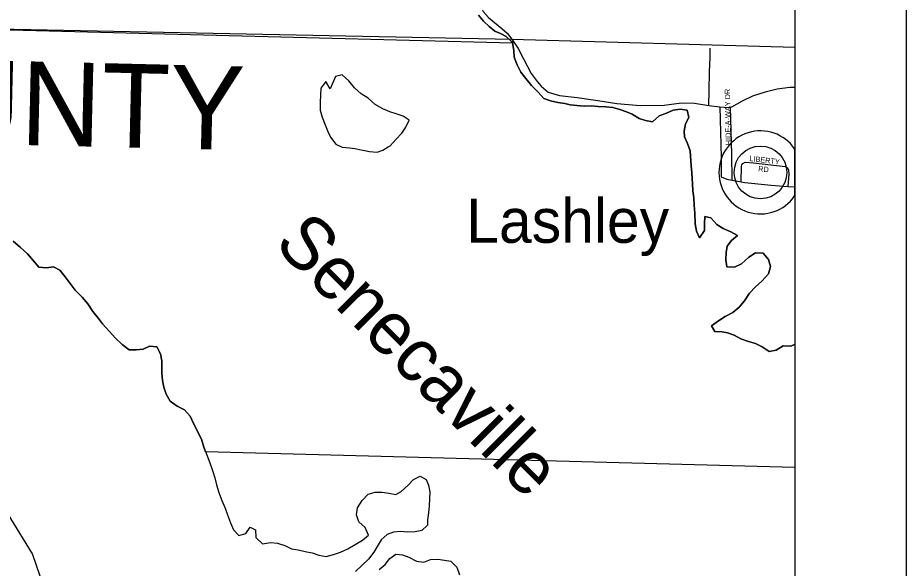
# Model space of a CAD drawing. Extents: x -22 to 431, y -18 to 160.
# Drawn here: x 330.402 to 331.995, y 157.754 to 158.739 of the extents above; entities that cross this region are included whole.
import ezdxf

# ---------------------------------------------------------------- set-up
doc = ezdxf.new("R2010")
doc.units = 0
for name, color, linetype in [('GM_X_Adjacent_County', 7, 'Continuous'), ('GM_X_Airport_Text_Class_2', 7, 'Continuous'), ('GM_X_County_ROW', 7, 'Continuous'), ('GM_X_County_Subdivision', 7, 'Continuous'), ('GM_X_Major_River_Text', 7, 'Continuous'), ('GM_X_Minor_River_Text', 7, 'Continuous'), ('GM_X_Section', 7, 'Continuous'), ('GM_X_Township_Road', 7, 'Continuous'), ('GM_X_Township_ROW', 7, 'Continuous'), ('GM_X_Township_Subdivision', 7, 'Continuous'), ('GM_X_Unincorporated_Text', 7, 'Continuous')]:
    doc.layers.add(name, color=color, linetype=linetype)

msp = doc.modelspace()

# ---------------------------------------------------------------- linework, layer by layer
at = {"layer": 'GM_X_County_ROW'}
for points in [[(331.1984, 158.868), (331.1996, 158.8569), (331.1999, 158.855), (331.2046, 158.8285), (331.2131, 158.8009), (331.2206, 158.7821), (331.2296, 158.7651), (331.2363, 158.7508), (331.246, 158.74), (331.2571, 158.731), (331.2698, 158.72), (331.2794, 158.7119), (331.2882, 158.7011)], [(331.2882, 158.7011), (331.299, 158.6846), (331.3091, 158.6657), (331.3227, 158.6394), (331.3334, 158.6256), (331.3405, 158.6168), (331.3529, 158.6064), (331.3733, 158.6004), (331.4051, 158.5969), (331.4422, 158.5915), (331.4763, 158.5862), (331.5179, 158.5822), (331.5612, 158.5828), (331.5923, 158.5869), (331.6156, 158.5868), (331.6409, 158.5825), (331.6605, 158.58), (331.6688, 158.5791), (331.6756, 158.5787), (331.6798, 158.5793), (331.6821, 158.5797), (331.7016, 158.5905), (331.7199, 158.5997), (331.7442, 158.6074), (331.7636, 158.6121), (331.786, 158.6152), (331.7949, 158.6152)], [(330.3922, 155.9159), (330.4518, 156.0381), (330.5552, 156.1431), (330.5592, 156.1465), (330.7531, 156.2605), (330.8962, 156.3618), (330.9146, 156.3744), (330.9622, 156.4236), (330.9704, 156.6616), (330.9659, 156.6885), (330.9511, 156.723), (330.9429, 156.7783), (330.9425, 156.8344), (330.9683, 156.9486), (330.9647, 156.9722), (330.9594, 156.9861), (330.9462, 156.9983), (330.4458, 157.5656), (330.4767, 157.6399), (330.4285, 157.7791), (330.323, 157.9508)]]:
    msp.add_lwpolyline(points, dxfattribs=at)
at = {"layer": 'GM_X_Major_River_Text'}
for p, q in [((330.1206, 158.7248), (331.2882, 158.7011)), ((331.2882, 158.7011), (331.7949, 158.6867))]:
    msp.add_line(p, q, dxfattribs=at)
at = {"layer": 'GM_X_Minor_River_Text'}
msp.add_lwpolyline([(331.6409, 158.5825), (331.6418, 158.6093), (331.6424, 158.6429), (331.6433, 158.6683), (331.6435, 158.6852)], dxfattribs=at)
at = {"layer": 'GM_X_Section'}
msp.add_line((331.7949, 159.9199), (331.7949, 147.6799), dxfattribs=at)
msp.add_lwpolyline([(319.3549, 160.1199), (331.9949, 160.1199), (331.9949, 147.4799), (319.3549, 147.4799)], close=True, dxfattribs=at)
at = {"layer": 'GM_X_Township_Road'}
msp.add_line((331.7949, 158.4203), (331.7949, 158.5048), dxfattribs=at)
msp.add_circle((331.7336, 158.4625), 0.0472, dxfattribs=at)
msp.add_arc((331.7336, 158.4625), 0.0744, 34.6154, 325.3846, dxfattribs=at)
at = {"layer": 'GM_X_Township_ROW'}
for points in [[(331.6605, 158.58), (331.663, 158.4894), (331.6629, 158.4548), (331.6731, 158.4503), (331.6829, 158.4485), (331.6987, 158.4457), (331.7057, 158.4445), (331.7526, 158.4395), (331.7825, 158.4373), (331.7949, 158.4364)], [(331.6829, 158.4485), (331.6823, 158.4954), (331.6798, 158.5793)], [(331.6987, 158.4457), (331.6993, 158.4734), (331.7004, 158.476), (331.702, 158.4787), (331.7061, 158.4809), (331.7209, 158.4798), (331.7781, 158.4732), (331.7819, 158.4705), (331.7841, 158.4663), (331.7845, 158.4591), (331.7825, 158.4373)]]:
    msp.add_lwpolyline(points, dxfattribs=at)
at = {"layer": 'GM_X_Township_Subdivision'}
for p, q in [((329.9956, 158.7279), (331.2892, 158.6947)), ((331.7949, 157.9339), (330.7391, 157.962))]:
    msp.add_line(p, q, dxfattribs=at)
for points in [[(331.2892, 158.6947), (331.2874, 158.6969), (331.2775, 158.7062), (331.2679, 158.711), (331.2573, 158.7155), (331.2474, 158.7241), (331.2374, 158.7334), (331.2279, 158.7439)], [(331.2279, 158.7439), (331.2374, 158.7334), (331.2474, 158.7241), (331.2573, 158.7155), (331.2679, 158.711), (331.2775, 158.7062), (331.2874, 158.6969), (331.2892, 158.6947)], [(331.7949, 158.1544), (331.7876, 158.1513), (331.774, 158.152), (331.7619, 158.1439), (331.7491, 158.1419), (331.7369, 158.1498), (331.7244, 158.1558), (331.7119, 158.1595), (331.6986, 158.1644), (331.6864, 158.1708), (331.6743, 158.1752), (331.6648, 158.1771), (331.6516, 158.1777), (331.6458, 158.1879), (331.6583, 158.1964), (331.6704, 158.2044), (331.6839, 158.2113), (331.6956, 158.2213), (331.705, 158.2327), (331.714, 158.246), (331.7249, 158.2575), (331.7362, 158.2674), (331.7479, 158.2811), (331.7516, 158.2937), (331.7477, 158.3062), (331.7382, 158.3179), (331.7246, 158.3182), (331.7125, 158.3105), (331.6993, 158.2987), (331.6869, 158.2925), (331.6736, 158.2936), (331.6713, 158.3061), (331.6719, 158.319), (331.6738, 158.3304), (331.6817, 158.3407), (331.6926, 158.3495), (331.6804, 158.3558), (331.6668, 158.3618), (331.6554, 158.3689), (331.6447, 158.3814), (331.6337, 158.3836), (331.6334, 158.3703), (331.6335, 158.3582), (331.6241, 158.3452), (331.6187, 158.3573), (331.6168, 158.3706), (331.6159, 158.3896), (331.615, 158.4036), (331.6142, 158.4169), (331.6122, 158.4297), (331.6118, 158.4423), (331.6114, 158.4517), (331.6105, 158.462), (331.6093, 158.4745), (331.6077, 158.501), (331.603, 158.5143), (331.5977, 158.5264), (331.5968, 158.5363), (331.599, 158.5492), (331.6054, 158.561), (331.6023, 158.5742), (331.5894, 158.5757), (331.5773, 158.5741), (331.5649, 158.5687), (331.552, 158.564), (331.5403, 158.5533), (331.5278, 158.5555), (331.5161, 158.5593), (331.5035, 158.5668), (331.4937, 158.5709), (331.4815, 158.575), (331.4687, 158.5787), (331.4565, 158.5798), (331.4425, 158.5808), (331.43, 158.5815), (331.4175, 158.5814), (331.4047, 158.5821), (331.3925, 158.5835), (331.3827, 158.5857), (331.3702, 158.5875), (331.3573, 158.5905), (331.3455, 158.595), (331.3349, 158.6063), (331.3231, 158.618), (331.3132, 158.6304), (331.304, 158.6418), (331.2975, 158.655), (331.2924, 158.6687), (331.2913, 158.6806), (331.2892, 158.6947)], [(331.2892, 158.6947), (331.2913, 158.6806), (331.2924, 158.6687), (331.2975, 158.655), (331.304, 158.6418), (331.3132, 158.6304), (331.3231, 158.618), (331.3349, 158.6063), (331.3455, 158.595), (331.3573, 158.5905), (331.3702, 158.5875), (331.3827, 158.5857), (331.3925, 158.5835), (331.4047, 158.5821), (331.4175, 158.5814), (331.43, 158.5815), (331.4425, 158.5808), (331.4565, 158.5798), (331.4687, 158.5787), (331.4815, 158.575), (331.4937, 158.5709), (331.5035, 158.5668), (331.5161, 158.5593), (331.5278, 158.5555), (331.5403, 158.5533), (331.552, 158.564), (331.5649, 158.5687), (331.5773, 158.5741), (331.5894, 158.5757), (331.6023, 158.5742), (331.6054, 158.561), (331.599, 158.5492), (331.5968, 158.5363), (331.5977, 158.5264), (331.603, 158.5143), (331.6077, 158.501), (331.6093, 158.4745), (331.6105, 158.462), (331.6114, 158.4517), (331.6118, 158.4423), (331.6122, 158.4297), (331.6142, 158.4169), (331.615, 158.4036), (331.6159, 158.3896), (331.6168, 158.3706), (331.6187, 158.3573), (331.6241, 158.3452), (331.6335, 158.3582), (331.6334, 158.3703), (331.6337, 158.3836), (331.6447, 158.3814), (331.6554, 158.3689), (331.6668, 158.3618), (331.6804, 158.3558), (331.6926, 158.3495), (331.6817, 158.3407), (331.6738, 158.3304), (331.6719, 158.319), (331.6713, 158.3061), (331.6736, 158.2936), (331.6869, 158.2925), (331.6993, 158.2987), (331.7125, 158.3105), (331.7246, 158.3182), (331.7382, 158.3179), (331.7477, 158.3062), (331.7516, 158.2937), (331.7479, 158.2811), (331.7362, 158.2674), (331.7249, 158.2575), (331.714, 158.246), (331.705, 158.2327), (331.6956, 158.2213), (331.6839, 158.2113), (331.6704, 158.2044), (331.6583, 158.1964), (331.6458, 158.1879), (331.6516, 158.1777), (331.6648, 158.1771), (331.6743, 158.1752), (331.6864, 158.1708), (331.6986, 158.1644), (331.7119, 158.1595), (331.7244, 158.1558), (331.7369, 158.1498), (331.7491, 158.1419), (331.7619, 158.1439), (331.774, 158.152), (331.7876, 158.1513), (331.7949, 158.1544)], [(331.0661, 158.508), (331.0699, 158.5102), (331.0808, 158.522), (331.0906, 158.533), (331.0981, 158.5433), (331.1037, 158.5563), (331.093, 158.5634), (331.0805, 158.5671), (331.0695, 158.5712), (331.0566, 158.5765), (331.0429, 158.5844), (331.0304, 158.5953), (331.0178, 158.6032), (331.006, 158.6141), (330.9957, 158.6266), (330.9839, 158.6371), (330.9718, 158.634), (330.9621, 158.612)], [(330.9621, 158.612), (330.9548, 158.6256), (330.9454, 158.6134), (330.9448, 158.6009), (330.9441, 158.588), (330.9445, 158.5739), (330.948, 158.5614), (330.9534, 158.5478), (330.958, 158.5357), (330.9626, 158.5258), (330.9725, 158.513), (330.9839, 158.5078), (330.9972, 158.5067), (331.0066, 158.5056), (331.018, 158.503), (331.0328, 158.5001), (331.0468, 158.499), (331.0566, 158.5025), (331.0661, 158.508)], [(330.394, 158.3393), (330.4073, 158.328), (330.4198, 158.3167), (330.4305, 158.3042), (330.44, 158.2925), (330.4537, 158.2918), (330.4665, 158.2934), (330.4775, 158.2871), (330.4871, 158.2757), (330.5054, 158.2516), (330.5176, 158.2391), (330.5282, 158.2271), (330.537, 158.2131), (330.5469, 158.201), (330.5542, 158.1912), (330.5668, 158.1776), (330.5771, 158.1659), (330.5892, 158.1543), (330.6018, 158.1449), (330.6143, 158.1449), (330.6271, 158.1458), (330.6385, 158.1515), (330.6517, 158.1501), (330.6579, 158.1376), (330.6606, 158.1248), (330.6603, 158.1122), (330.6603, 158.1028), (330.6619, 158.0899), (330.6639, 158.0777), (330.6685, 158.0653), (330.6758, 158.0528), (330.6883, 158.0438), (330.7012, 158.0374), (330.7111, 158.0261), (330.718, 158.0117), (330.7318, 157.9845), (330.7361, 157.9705), (330.7418, 157.9546), (330.7464, 157.9425), (330.7514, 157.9288), (330.7557, 157.9152), (330.7588, 157.9031), (330.7627, 157.8891), (330.768, 157.8751), (330.7742, 157.8611), (330.7784, 157.8494), (330.7834, 157.835), (330.7888, 157.8221), (330.7987, 157.8123), (330.8112, 157.8158), (330.8187, 157.8272), (330.8282, 157.8224), (330.829, 157.8087), (330.8408, 157.7974)], [(330.7391, 157.962), (330.7361, 157.9705), (330.7318, 157.9845), (330.718, 158.0117), (330.7111, 158.0261), (330.7012, 158.0374), (330.6883, 158.0438), (330.6758, 158.0528), (330.6685, 158.0653), (330.6639, 158.0777), (330.6619, 158.0899), (330.6603, 158.1028), (330.6603, 158.1122), (330.6606, 158.1248), (330.6579, 158.1376), (330.6517, 158.1501), (330.6385, 158.1515), (330.6271, 158.1458), (330.6143, 158.1449), (330.6018, 158.1449), (330.5892, 158.1543), (330.5771, 158.1659), (330.5668, 158.1776), (330.5542, 158.1912), (330.5469, 158.201), (330.537, 158.2131), (330.5282, 158.2271), (330.5176, 158.2391), (330.5054, 158.2516), (330.4871, 158.2757), (330.4775, 158.2871), (330.4665, 158.2934), (330.4537, 158.2918), (330.44, 158.2925), (330.4305, 158.3042), (330.4198, 158.3167), (330.4073, 158.328), (330.394, 158.3393)], [(330.8408, 157.7974), (330.8552, 157.7994), (330.868, 157.7984), (330.8809, 157.7943), (330.8927, 157.7883), (330.9048, 157.7865), (330.9173, 157.7835), (330.9298, 157.7809), (330.942, 157.7772), (330.9552, 157.7746), (330.9685, 157.7781), (330.9806, 157.7824), (330.9938, 157.7885), (331.0074, 157.7958), (331.0202, 157.8039), (331.0311, 157.8127), (331.025, 157.8263), (331.0139, 157.8365), (331.0097, 157.8493), (331.0111, 157.8619), (331.0198, 157.8748), (331.0303, 157.8859), (331.0428, 157.8898), (331.0556, 157.8895), (331.0677, 157.888), (331.0799, 157.8858), (331.0897, 157.8912), (331.1021, 157.9023), (331.1115, 157.9122), (331.1236, 157.9187), (331.1346, 157.9127), (331.1388, 157.9025), (331.1408, 157.8904), (331.1405, 157.8779), (331.1398, 157.8653), (331.1387, 157.8528), (331.1369, 157.8403), (331.1366, 157.8308), (331.1264, 157.8209), (331.1147, 157.8189), (331.1015, 157.8181), (331.0886, 157.8195), (331.0761, 157.8183), (331.0644, 157.8137), (331.0535, 157.8045), (331.0467, 157.7927), (331.0404, 157.782), (331.031, 157.7698), (331.0193, 157.7587), (331.008, 157.7477)], [(331.0504, 157.751), (331.0606, 157.7605), (331.0692, 157.7708), (331.0798, 157.7785), (331.0922, 157.7774), (331.1036, 157.7733), (331.1169, 157.7662), (331.1302, 157.7644), (331.1419, 157.769), (331.1551, 157.7699), (331.1672, 157.768), (331.1786, 157.7662), (331.1893, 157.7557), (331.1939, 157.7417)]]:
    msp.add_lwpolyline(points, dxfattribs=at)

# ---------------------------------------------------------------- texts
at = {"layer": 'GM_X_Adjacent_County'}
msp.add_text('Lashley', height=0.07891, rotation=0, dxfattribs=at).set_placement((331.2062, 158.3364))
at = {"layer": 'GM_X_Airport_Text_Class_2'}
msp.add_text('Senecaville', height=0.094697, rotation=315.0021, dxfattribs=at).set_placement((330.8594, 158.3321))
at = {"layer": 'GM_X_County_Subdivision'}
for s, rotation, p in [('HIDE-A-WAY DR', 91.0603, (331.6808, 158.5113)), ('LIBERTY', 353.2341, (331.7134, 158.483)), ('RD', 353.9832, (331.7292, 158.4646))]:
    msp.add_text(s, height=0.00947, rotation=rotation, dxfattribs=at).set_placement(p)
at = {"layer": 'GM_X_Unincorporated_Text'}
msp.add_text('NOBLE COUNTY', height=0.15, rotation=358.6249, dxfattribs=at).set_placement((329.2247, 158.5401))

doc.saveas('drawing.dxf')
